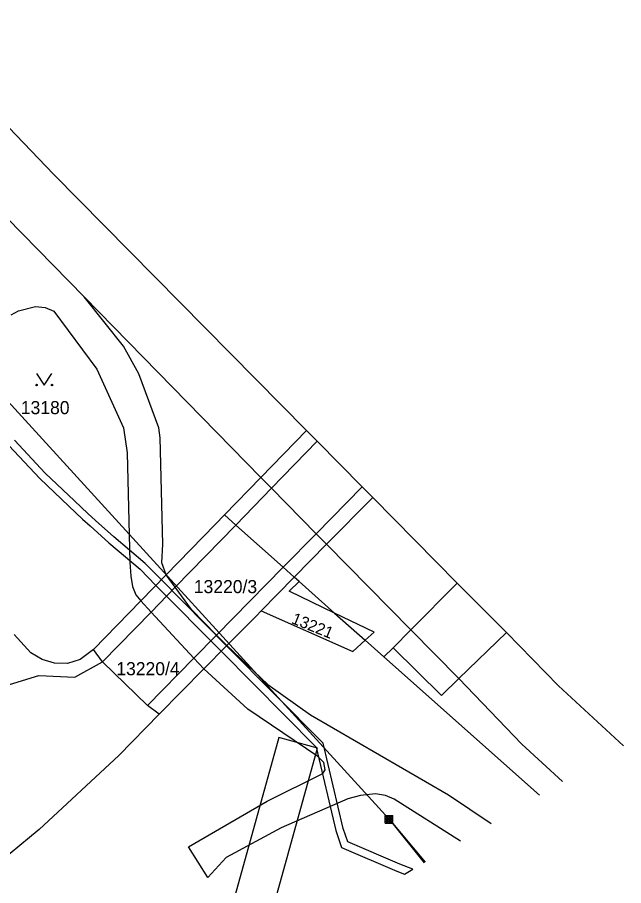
# Model space of a CAD drawing. Extents: x -821458 to -820266, y -1071458 to -1069826.
# Drawn here: x -820345.1 to -820266.4, y -1071261.9 to -1071149.2 of the extents above; entities that cross this region are included whole.
import ezdxf

# ---------------------------------------------------------------- set-up
doc = ezdxf.new("R2010")
doc.units = 0
for name, color, linetype in [('Vrstva 1', 7, 'Continuous'), ('Vrstva 13', 7, 'Continuous'), ('Vrstva 2', 7, 'Continuous'), ('Vrstva 3', 7, 'Continuous'), ('Vrstva 4', 7, 'Continuous'), ('Vrstva 6', 7, 'Continuous')]:
    doc.layers.add(name, color=color, linetype=linetype)

msp = doc.modelspace()

# ---------------------------------------------------------------- linework, layer by layer
at = {"layer": 'Vrstva 1'}
for p, q in [((-820307.59, -1071202.82), (-820340.44, -1071169.52)), ((-820309.18, -1071221.87), (-820313.47, -1071226.22)), ((-820308.54, -1071222.44), (-820309.18, -1071221.87)), ((-820335.23, -1071231.26), (-820329.1, -1071224.95)), ((-820334.05, -1071232.87), (-820335.23, -1071231.26)), ((-820320.91, -1071233.77), (-820326.72, -1071239.67))]:
    msp.add_line(p, q, dxfattribs=at)
for points in [[(-820340.44, -1071169.52), (-820353.06, -1071156.4), (-820360.13, -1071149.18)], [(-820347, -1071174.7), (-820346.49, -1071175.21), (-820336.47, -1071185.46)], [(-820325.81, -1071221.57), (-820326.37, -1071220.01), (-820326.22, -1071217.58), (-820326.57, -1071203.78), (-820326.74, -1071202.48), (-820329.37, -1071195.47), (-820331.36, -1071191.86), (-820336.47, -1071185.46)], [(-820336.47, -1071185.46), (-820313.52, -1071208.92), (-820312.14, -1071210.33), (-820306.35, -1071216.23), (-820305, -1071217.6), (-820294.06, -1071228.7), (-820287.81, -1071235.03), (-820279.64, -1071243.56), (-820274.37, -1071248.41)], [(-820345.92, -1071187.79), (-820344.96, -1071187.27), (-820342.78, -1071186.74), (-820341.52, -1071186.84), (-820340.4, -1071187.31), (-820334.81, -1071194.86), (-820331.35, -1071202.47), (-820330.87, -1071205.72), (-820330.53, -1071219.91), (-820330.4, -1071221.75), (-820330.19, -1071223.09), (-820329.73, -1071224.17), (-820329.1, -1071224.95)], [(-820266.44, -1071243.76), (-820274.89, -1071235.98), (-820281.64, -1071229.04), (-820288.05, -1071222.63), (-820299.01, -1071211.52), (-820300.37, -1071210.14), (-820306.21, -1071204.22), (-820307.59, -1071202.82)], [(-820325.81, -1071221.57), (-820319.46, -1071215.04), (-820318.25, -1071213.79), (-820316.78, -1071215.1), (-820310.63, -1071220.58), (-820309.18, -1071221.87)], [(-820317.93, -1071230.75), (-820319.27, -1071229.38), (-820322.5, -1071226.08), (-820324.63, -1071223.18), (-820325.81, -1071221.57)], [(-820303.95, -1071226.53), (-820309.86, -1071223.69), (-820308.54, -1071222.44)], [(-820329.1, -1071224.95), (-820327.76, -1071226.4), (-820322.21, -1071232.37), (-820320.91, -1071233.77)], [(-820313.47, -1071226.22), (-820314.15, -1071226.91), (-820317.93, -1071230.75)], [(-820313.47, -1071226.22), (-820301.6, -1071231.5), (-820299.99, -1071230.06)], [(-820299.99, -1071230.06), (-820298.8, -1071229), (-820303.95, -1071226.53)], [(-820335.23, -1071231.26), (-820336.97, -1071232.55), (-820338.6, -1071233.07), (-820340.31, -1071233.04), (-820341.92, -1071232.55), (-820343.38, -1071231.68), (-820345.52, -1071229.33)], [(-820277.38, -1071250.17), (-820297.55, -1071232.23), (-820299.99, -1071230.06)], [(-820317.93, -1071230.75), (-820312.63, -1071235.79), (-820307.09, -1071239.72), (-820289.19, -1071250.11), (-820283.65, -1071253.85)], [(-820347.25, -1071236.15), (-820342.32, -1071234.63), (-820337.67, -1071234.87), (-820334.05, -1071232.87)], [(-820326.72, -1071239.67), (-820328.23, -1071238.51), (-820334.05, -1071232.87)], [(-820287.6, -1071256.16), (-820296.23, -1071250.69), (-820297.33, -1071250.2), (-820298.63, -1071249.99), (-820300.57, -1071250.21), (-820302.24, -1071250.66), (-820310.89, -1071254.41), (-820318.01, -1071258.27), (-820320.42, -1071260.84), (-820322.89, -1071256.87), (-820312.7, -1071250.94), (-820305.48, -1071247.35), (-820305.18, -1071246.87), (-820305.33, -1071245.91), (-820306.12, -1071245.17), (-820315.21, -1071239), (-820320.91, -1071233.77)], [(-820326.72, -1071239.67), (-820331.97, -1071245.01), (-820342.31, -1071254.65), (-820353.61, -1071263.96), (-820360.02, -1071268.97), (-820360.98, -1071270.3), (-820361.65, -1071272.32), (-820361.24, -1071273.9), (-820360.23, -1071275.23)]]:
    msp.add_lwpolyline(points, dxfattribs=at)
at = {"layer": 'Vrstva 13'}
msp.add_line((-820294.89, -1071260.44), (-820293.8, -1071259.8), dxfattribs=at)
for points in [[(-820293.8, -1071259.8), (-820295.49, -1071259.12), (-820302.24, -1071256.21), (-820302.82, -1071254.48), (-820305.43, -1071243.44), (-820317.96, -1071230.77), (-820326.43, -1071222.21), (-820328.52, -1071220.09), (-820332.61, -1071216.65), (-820334.99, -1071214.49), (-820335.97, -1071213.6), (-820337.71, -1071211.96), (-820341.51, -1071208.35), (-820345.51, -1071204.08)], [(-820346.23, -1071204.78), (-820342.21, -1071209.05), (-820338.45, -1071212.63), (-820336.65, -1071214.34), (-820335.69, -1071215.21), (-820333.27, -1071217.41), (-820329.2, -1071220.83), (-820327.13, -1071222.93), (-820318.66, -1071231.48), (-820306.33, -1071243.94), (-820303.78, -1071254.76), (-820303.04, -1071256.95), (-820295.87, -1071260.04), (-820294.89, -1071260.44)], [(-820313.77, -1071271.5), (-820306.15, -1071244.05), (-820311.18, -1071242.67), (-820320.21, -1071275.28)]]:
    msp.add_lwpolyline(points, dxfattribs=at)
at = {"layer": 'Vrstva 3'}
msp.add_lwpolyline([(-820342.63, -1071195.42), (-820341.63, -1071196.92), (-820340.63, -1071195.42)], dxfattribs=at)
for centre in [(-820342.63, -1071196.92), (-820340.63, -1071196.92)]:
    msp.add_circle(centre, 0.1, dxfattribs=at)
at = {"layer": 'Vrstva 4'}
for p, q in [((-820313.52, -1071208.92), (-820307.59, -1071202.82)), ((-820306.21, -1071204.22), (-820312.14, -1071210.33)), ((-820318.25, -1071213.79), (-820313.52, -1071208.92)), ((-820312.14, -1071210.33), (-820316.78, -1071215.1)), ((-820300.37, -1071210.14), (-820306.35, -1071216.23)), ((-820305, -1071217.6), (-820299.01, -1071211.52)), ((-820316.78, -1071215.1), (-820324.63, -1071223.18)), ((-820306.35, -1071216.23), (-820310.63, -1071220.58)), ((-820309.18, -1071221.87), (-820305, -1071217.6)), ((-820310.63, -1071220.58), (-820319.27, -1071229.38)), ((-820325.81, -1071221.57), (-820329.1, -1071224.95)), ((-820324.63, -1071223.18), (-820327.76, -1071226.4)), ((-820308.54, -1071222.44), (-820303.95, -1071226.53)), ((-820294.06, -1071228.7), (-820288.05, -1071222.63)), ((-820327.76, -1071226.4), (-820334.05, -1071232.87)), ((-820303.95, -1071226.53), (-820299.99, -1071230.06)), ((-820296.33, -1071231.02), (-820294.06, -1071228.7)), ((-820319.27, -1071229.38), (-820322.21, -1071232.37)), ((-820281.64, -1071229.04), (-820287.81, -1071235.03)), ((-820317.93, -1071230.75), (-820320.91, -1071233.77)), ((-820297.55, -1071232.23), (-820296.33, -1071231.02)), ((-820290.07, -1071237.23), (-820296.33, -1071231.02)), ((-820322.21, -1071232.37), (-820328.23, -1071238.51)), ((-820287.81, -1071235.03), (-820290.07, -1071237.23))]:
    msp.add_line(p, q, dxfattribs=at)
at = {"layer": 'Vrstva 6'}
for p, q in [((-820349.5, -1071195.59), (-820296.89, -1071253.29)), ((-820297.39, -1071252.79), (-820296.39, -1071252.79)), ((-820297.39, -1071253.79), (-820297.39, -1071252.79)), ((-820297.39, -1071252.99), (-820296.39, -1071252.99)), ((-820297.39, -1071253.19), (-820296.39, -1071253.19)), ((-820297.39, -1071253.39), (-820296.39, -1071253.39)), ((-820297.39, -1071253.59), (-820296.39, -1071253.59)), ((-820297.39, -1071253.79), (-820296.39, -1071253.79)), ((-820297.19, -1071253.79), (-820297.19, -1071252.79)), ((-820296.99, -1071253.79), (-820296.99, -1071252.79)), ((-820296.89, -1071253.29), (-820292.2, -1071258.86)), ((-820296.89, -1071253.29), (-820292.34, -1071258.94)), ((-820296.79, -1071253.79), (-820296.79, -1071252.79)), ((-820296.59, -1071253.79), (-820296.59, -1071252.79)), ((-820296.39, -1071253.79), (-820296.39, -1071252.79))]:
    msp.add_line(p, q, dxfattribs=at)

# ---------------------------------------------------------------- texts
at = {"layer": 'Vrstva 2'}
for s, p in [('13180', (-820344.67, -1071200.7)), ('13220/3', (-820322.22, -1071223.94)), ('13220/4', (-820332.28, -1071234.6))]:
    msp.add_text(s, height=1.7, dxfattribs=at).set_placement(p)
msp.add_text('13221', height=1.5, rotation=338, dxfattribs=at).set_placement((-820309.66, -1071227.81))

doc.saveas('drawing.dxf')
